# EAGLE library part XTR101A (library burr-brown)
Precision, Low Drift 4-20mA Two-Wire Transmitter
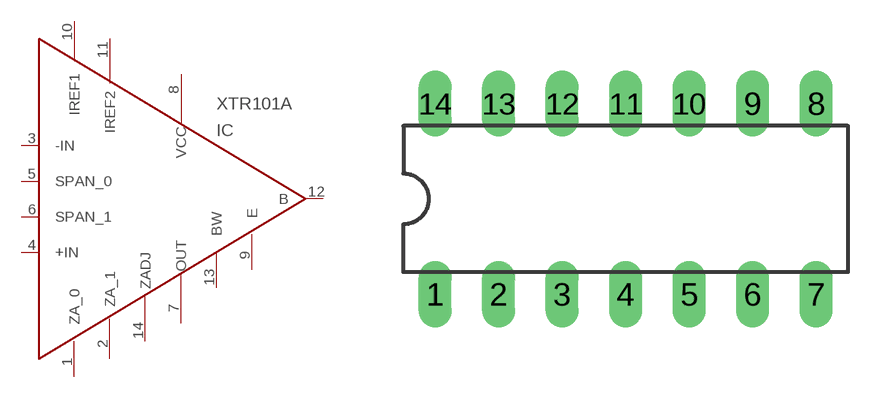
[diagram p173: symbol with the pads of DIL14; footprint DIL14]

Designator prefix IC

## XTR101A (MF: TEXAS INSTRUMENTS; MPN: XTR101AP; OC_FARNELL: 1648756; OC_NEWARK: 84K4518)  [DIL14]
1  ZA_0  pas
2  ZA_1  pas
3  -IN  in
4  +IN  in
5  SPAN_0  pas
6  SPAN_1  pas
7  OUT  out
8  VCC  pwr
9  E  out
10  IREF1  in
11  IREF2  in
12  B  out
13  BW  out
14  ZADJ  out

## Footprint DIL14 (pad centres in mm)
Dual In Line Package
drill 0.813 long: 1 -7.62,-3.81; 2 -5.08,-3.81; 3 -2.54,-3.81; 4 0,-3.81; 5 2.54,-3.81; 6 5.08,-3.81; 7 7.62,-3.81; 8 7.62,3.81; 9 5.08,3.81; 10 2.54,3.81; 11 0,3.81; 12 -2.54,3.81; 13 -5.08,3.81; 14 -7.62,3.81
